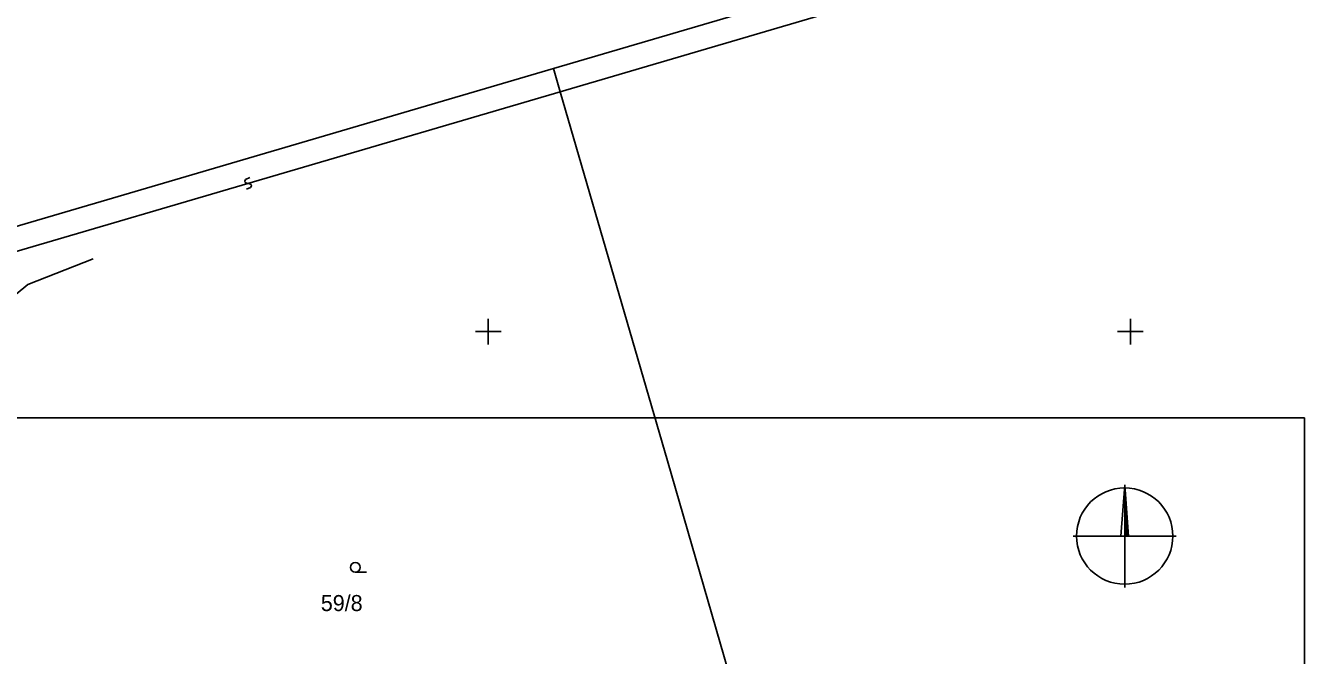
# Model space of a CAD drawing. Extents: x -651478 to -651308, y -994378 to -994071.
# Drawn here: x -651414.41 to -651374.58, y -994250.09 to -994230.47 of the extents above; entities that cross this region are included whole.
import ezdxf

# ---------------------------------------------------------------- set-up
doc = ezdxf.new("R2010")
doc.units = 0
for name, color, linetype in [('30_EL-VEDENI', 7, 'Continuous'), ('_KM', 7, 'Continuous'), ('rezy', 7, 'Continuous'), ('ROZP', 7, 'Continuous')]:
    doc.layers.add(name, color=color, linetype=linetype)

# ---------------------------------------------------------------- blocks, each defined once
blk = doc.blocks.new('Z3040')
blk.add_line((0, 0), (0.35, 0))
blk.add_circle((0, 0.15), 0.15)
blk = doc.blocks.new('Z218')
for p, q in [((-0.04, 0.14), (-0.08, 0.1)), ((-0.08, 0.1), (-0.08, 0.06)), ((-0.08, 0.06), (-0.04, 0.02)), ((0.1, 0.16), (-0.04, 0.14)), ((-0.04, 0.02), (0.04, -0.02)), ((0.04, -0.14), (-0.1, -0.16)), ((0.04, -0.02), (0.08, -0.06)), ((0.08, -0.1), (0.04, -0.14)), ((0.08, -0.06), (0.08, -0.1))]:
    blk.add_line(p, q)
blk = doc.blocks.new('Z70')
for p, q in [((0, -0.4), (0, 0.4)), ((-0.4, 0), (0.4, 0))]:
    blk.add_line(p, q)

msp = doc.modelspace()

# ---------------------------------------------------------------- linework, layer by layer
at = {"layer": '30_EL-VEDENI'}
for p, q in [((-651414.34, -994238.53), (-651412.303, -994237.737)), ((-651415.94, -994239.86), (-651414.34, -994238.53))]:
    msp.add_line(p, q, dxfattribs=at)
at = {"layer": '_KM'}
for p, q in [((-651384.86, -994227.95), (-651397.97, -994231.8)), ((-651397.76, -994232.53), (-651382.1, -994227.92)), ((-651397.97, -994231.8), (-651417.89, -994237.66)), ((-651397.76, -994232.53), (-651397.97, -994231.8)), ((-651417.67, -994238.38), (-651397.76, -994232.53)), ((-651394.42, -994244.03), (-651397.76, -994232.53)), ((-651391.13, -994255.35), (-651394.42, -994244.03))]:
    msp.add_line(p, q, dxfattribs=at)
at = {"layer": 'rezy'}
for p, q in [((-651374.583, -994242.69), (-651433.983, -994242.69)), ((-651374.583, -994326.69), (-651374.583, -994242.69)), ((-651380.18, -994244.768), (-651380.295, -994246.368)), ((-651380.18, -994244.768), (-651380.063, -994246.368)), ((-651380.18, -994244.768), (-651380.18, -994247.968)), ((-651380.171, -994244.992), (-651380.073, -994246.358)), ((-651380.167, -994246.355), (-651380.171, -994244.992)), ((-651380.164, -994245.215), (-651380.084, -994246.351)), ((-651380.157, -994246.344), (-651380.164, -994245.215)), ((-651380.153, -994245.473), (-651380.094, -994246.337)), ((-651380.15, -994246.337), (-651380.153, -994245.473)), ((-651380.143, -994245.741), (-651380.105, -994246.327)), ((-651380.139, -994246.33), (-651380.143, -994245.741)), ((-651380.129, -994246.041), (-651380.115, -994246.309)), ((-651380.129, -994246.32), (-651380.129, -994246.041)), ((-651381.78, -994246.368), (-651378.58, -994246.368)), ((-651380.063, -994246.368), (-651380.167, -994246.355)), ((-651380.073, -994246.358), (-651380.157, -994246.344)), ((-651380.084, -994246.351), (-651380.15, -994246.337)), ((-651380.094, -994246.337), (-651380.139, -994246.33)), ((-651380.105, -994246.327), (-651380.129, -994246.32))]:
    msp.add_line(p, q, dxfattribs=at)
msp.add_circle((-651380.18, -994246.368), 1.5, dxfattribs=at)

# ---------------------------------------------------------------- block references
at = {"layer": '_KM', "rotation": -163.62600000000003}
msp.add_blockref('Z218', (-651407.475, -994235.385), dxfattribs=at)
at = {"layer": '_KM'}
msp.add_blockref('Z3040', (-651404.136, -994247.494), dxfattribs=at)
at = {"layer": 'ROZP'}
for p in [(-651400, -994240), (-651380, -994240)]:
    msp.add_blockref('Z70', p, dxfattribs=at)

# ---------------------------------------------------------------- texts
at = {"layer": '_KM'}
msp.add_text('59/8', height=0.5, dxfattribs=at).set_placement((-651405.211, -994248.706))

doc.saveas('drawing.dxf')
